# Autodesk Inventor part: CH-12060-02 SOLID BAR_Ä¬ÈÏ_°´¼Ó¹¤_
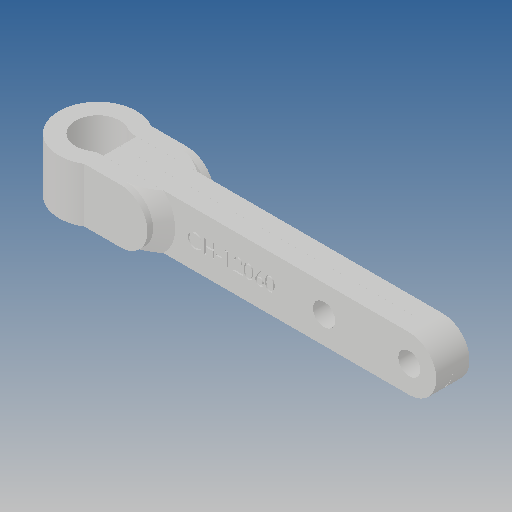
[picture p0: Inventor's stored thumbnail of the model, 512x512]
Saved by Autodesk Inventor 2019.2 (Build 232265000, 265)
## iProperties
Created: 2015-08
Part Number: CH-12060-02 SOLID BAR_Ä¬ÈÏ_°´¼Ó¹¤_
Material: Ogólny
Document SubType Name: Modeling
Designer: CADENGINEERING4
Density: 1 g/cm^3
Appearance: Domyślna
Author: CADENGINEERING4
Revision Number: ÈÎºÎ
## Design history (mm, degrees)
feature "Ô²½Ç1"
feature "Ô²½Çº¸·ì1"
feature "Ô²½Çº¸·ì2"
feature "À­Éì3"
feature "À­Éì6"
node "Bryła1"
node "Bryła2"
node "Bryła3"
node "Bryła4"
node "Bryła5"
